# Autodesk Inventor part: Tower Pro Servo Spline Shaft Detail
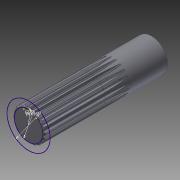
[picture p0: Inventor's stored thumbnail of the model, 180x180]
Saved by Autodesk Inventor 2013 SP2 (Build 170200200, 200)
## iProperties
Created: 2020-02
Part Number: Tower Pro Servo Spline Shaft Detail
Material: Steel
Document SubType Name: Modeling
Designer: DELL
Density: 1 g/cm^3
CustomPartVersion: 1
Author: DELL
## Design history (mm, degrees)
sketch "Sketch3"
  geometry: C1 r 2.6 at (0, 0); 1 further point
  constraints: 1 centre point, 1 coincident
  dimensions: "d16" = 5.2 diameter of C1
extrude "Extrusion1" new body sketch "Sketch3" distance "d18" = 20; taper "d19" = 0 deg
chamfer "Chamfer4" distance "d21" = 0.25; stored, may be unused: second distance "d22" = 2, angle "d23" = 45 deg
sketch "Sketch4"
  geometry: L1 (0, 0)-(1.12, 2.704); L2 (0, -3.751)-(0, 3.779) reference; L3 (0, 0)-(-1.12, 2.704); L4 (0.643, 1.552)-(-1.571, 2.469); C1 r 2.375 at (0, 0); C2 r 2.475 at (0, 0); C3 r 2.183 at (0, 0); C4 r 1.68 at (0, 0); 1 further point
  constraints: 6 end point, 4 centre point, 4 coincident, 1 perpendicular, 1 point on line, 1 tangent
  dimensions: "d46" = 4.75 diameter of C1; "d48" = 4.95 diameter of C2; "d49" = 4.367 diameter of C3; "d50" = 3.359 diameter of C4; "d52" = 22.5 deg angle of L1 L2; "d53" = 45 deg angle of L1 L3
sketch "Sketch5"
  geometry: L1 (0, -1.686)-(-0.333, -2.668); L2 (0, -1.686)-(0.336, -2.675); L3 (0, -3.751)-(0, 3.779) reference; 5 further points
  constraints: 4 end point, 2 other
  dimensions: "d54" = 1.6862 distance of L1.start point (0, 0); "d55" = 18.75 deg angle of L2 L3; "d56" = 18.75 deg angle of L3 L1 (= d55); "d57" = 37.5 deg angle of L2 L1 (derived)
node "Involute Splining9"
sketch "Sketch6" dims "d64" = 4.61623 (derived)
  geometry: C1 r 3.5 at (0, 0); A1 r 2.308 centre (0, 0) between (0.414, 2.271) and (0.308, 2.287) reference; A2 r 1.037 centre (-0.708, 1.95) between (0.259, 2.327) and (0.255, 2.336) reference; A3 r 0.063 centre (0.317, 2.349) between (0.259, 2.327) and (0.308, 2.287) reference; A4 r 0.062 centre (0.425, 2.332) between (0.414, 2.271) and (0.473, 2.293) reference; A5 r 1.037 centre (1.276, 1.636) between (0.48, 2.301) and (0.473, 2.293) reference; A6 r 1.037 centre (1.276, 1.636) between (0.706, 2.502) and (0.473, 2.293) reference; A7 r 2.6 centre (0, 0) between (0.706, 2.502) and (0.102, 2.598); 2 further points
  constraints: 3 coincident, 2 centre point, 2 point on circle, 4 other
  dimensions: "d61" = 7 diameter of C1; "d63" = 2.6 radius of A7 (derived)
body "Solid2"
feature "Shaft Groove"
